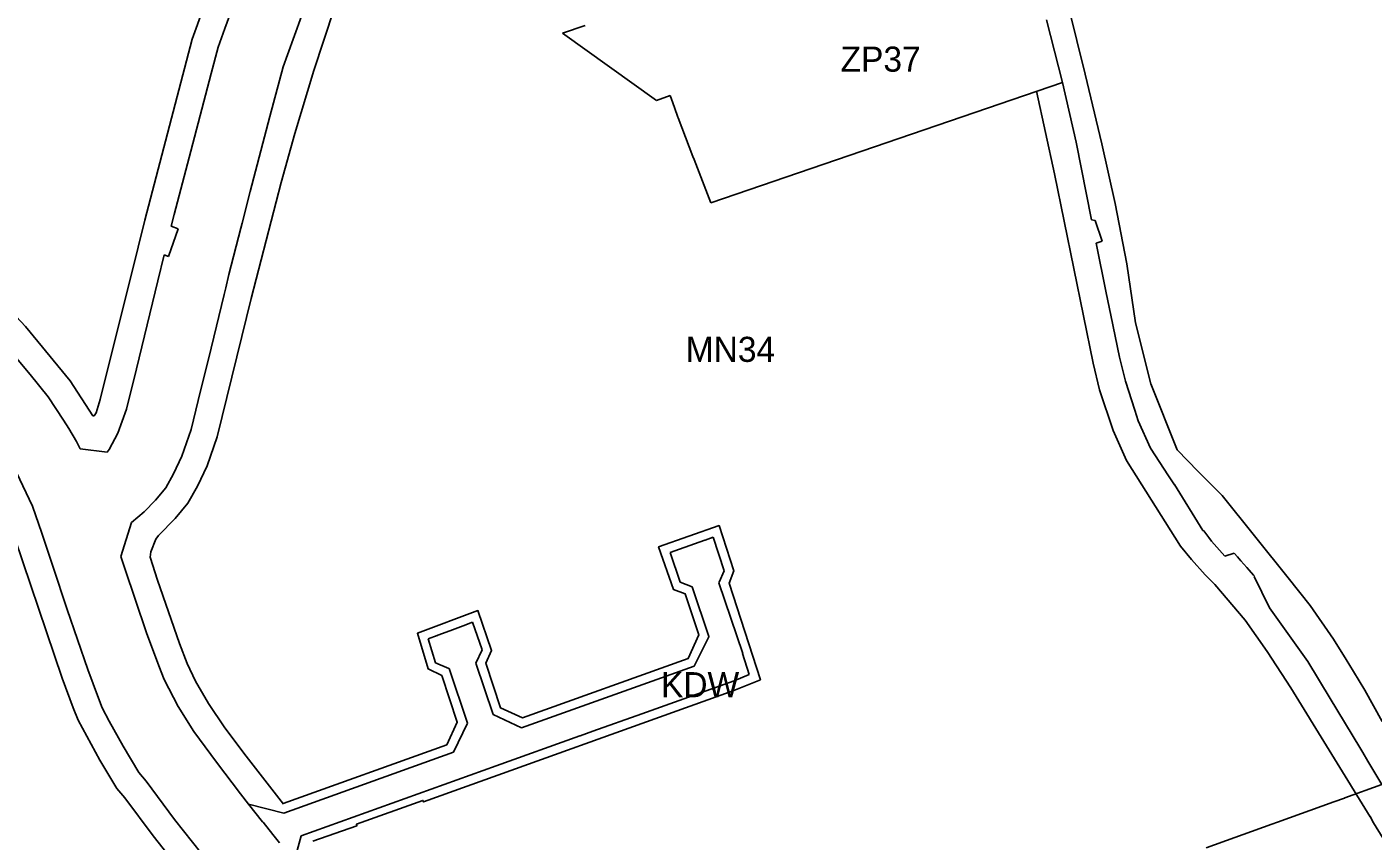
# Model space of a CAD drawing. Extents: x 7428080 to 7432143, y 5545880 to 5549217.
# Drawn here: x 7430887.1 to 7431185, y 5546851.1 to 5547031.3 of the extents above; entities that cross this region are included whole.
import ezdxf

# ---------------------------------------------------------------- set-up
doc = ezdxf.new("R2010")
doc.units = 0
for name, color, linetype in [('CZ_L_granica obszaru objętego planem', 7, 'Continuous'), ('CZ_L_linie rozgraniczające tereny o różnym przeznaczeniu oraz różnych warunkach ich zabudowy i zagospodarowania', 7, 'Continuous'), ('CZ_L_maksymalne nieprzekraczalne linie zabudowy', 7, 'Continuous'), ('CZ_L_opisy_linie rozgraniczające tereny o różnym przeznaczeniu oraz różnych warunkach ich zabudowy i zagospodarowania', 7, 'Continuous')]:
    doc.layers.add(name, color=color, linetype=linetype)

msp = doc.modelspace()

# ---------------------------------------------------------------- linework, layer by layer
at = {"layer": 'CZ_L_granica obszaru objętego planem'}
for p, q in [((7431117.61, 5547035.75), (7431121.32, 5547020.82)), ((7431121.32, 5547020.82), (7431125.01, 5547005.39)), ((7431125.01, 5547005.39), (7431127.96, 5546992.25)), ((7431127.96, 5546992.25), (7431130.5, 5546978.83)), ((7431130.5, 5546978.83), (7431132.44, 5546965.83)), ((7431132.44, 5546965.83), (7431135.86, 5546952.34)), ((7431135.86, 5546952.34), (7431141.66, 5546937.67)), ((7431141.66, 5546937.67), (7431146.32, 5546932.9)), ((7431146.32, 5546932.9), (7431151.59, 5546927.62)), ((7431151.59, 5546927.62), (7431166.27, 5546909.37)), ((7431166.27, 5546909.37), (7431171.08, 5546903.28)), ((7431171.08, 5546903.28), (7431176.28, 5546895.82)), ((7431176.28, 5546895.82), (7431179.09, 5546891.28)), ((7431179.09, 5546891.28), (7431180.72, 5546888.65)), ((7431180.72, 5546888.65), (7431183.18, 5546884.54)), ((7431183.18, 5546884.54), (7431187.05, 5546877.6))]:
    msp.add_line(p, q, dxfattribs=at)
at = {"layer": 'CZ_L_linie rozgraniczające tereny o różnym przeznaczeniu oraz różnych warunkach ich zabudowy i zagospodarowania'}
for p, q in [((7430936.02, 5547045.16), (7430930.9, 5547030.96)), ((7430949.44, 5547038.17), (7430944.73, 5547025.11)), ((7431112.76, 5547032.83), (7431116.28, 5547019.02)), ((7430930.9, 5547030.96), (7430929.41, 5547026.79)), ((7431005.65, 5547029.91), (7431010.64, 5547031.63)), ((7431026.39, 5547015), (7431005.65, 5547029.91)), ((7430929.41, 5547026.79), (7430927.87, 5547020.98)), ((7430944.73, 5547025.11), (7430943.77, 5547022.44)), ((7430927.87, 5547020.98), (7430923.36, 5547003.83)), ((7430943.77, 5547022.44), (7430940.87, 5547011.44)), ((7431116.26, 5547019.01), (7431038.48, 5546992.34)), ((7431116.28, 5547019.02), (7431116.26, 5547019.01)), ((7431119.3, 5547005.78), (7431116.26, 5547019.01)), ((7431029.46, 5547016.12), (7431026.39, 5547015)), ((7431030.02, 5547014.46), (7431029.46, 5547016.12)), ((7431030.99, 5547011.78), (7431030.02, 5547014.46)), ((7431031.15, 5547011.36), (7431030.99, 5547011.78)), ((7430940.87, 5547011.44), (7430936.51, 5546994.87)), ((7431031.21, 5547011.17), (7431031.15, 5547011.36)), ((7431034.49, 5547002.62), (7431031.21, 5547011.17)), ((7431122.71, 5546988.6), (7431119.3, 5547005.78)), ((7430923.36, 5547003.83), (7430919.67, 5546989.77)), ((7431034.75, 5547001.96), (7431034.49, 5547002.62)), ((7431038.48, 5546992.34), (7431034.75, 5547001.96)), ((7430936.51, 5546994.87), (7430934.68, 5546987.9)), ((7430919.67, 5546989.77), (7430919.02, 5546987.17)), ((7430934.68, 5546987.9), (7430934.39, 5546986.78)), ((7431123.53, 5546988.45), (7431122.71, 5546988.6)), ((7431125.1, 5546983.87), (7431123.53, 5546988.45)), ((7430920.58, 5546986.61), (7430918.44, 5546980.5)), ((7430919.02, 5546987.17), (7430920.58, 5546986.61)), ((7430934.4, 5546986.77), (7430931.8, 5546976.53)), ((7430934.39, 5546986.78), (7430934.4, 5546986.77)), ((7431123.75, 5546983.44), (7431125.1, 5546983.87)), ((7431125.96, 5546972.48), (7431123.75, 5546983.44)), ((7430917.45, 5546980.85), (7430916.02, 5546975.09)), ((7430918.44, 5546980.5), (7430917.45, 5546980.85)), ((7430931.8, 5546976.53), (7430931.07, 5546973.52)), ((7430916.02, 5546975.09), (7430911.29, 5546955.65)), ((7430931.07, 5546973.52), (7430930.72, 5546972.09)), ((7430930.72, 5546972.09), (7430927.83, 5546960.2)), ((7431126.97, 5546967.49), (7431125.96, 5546972.48)), ((7431128.88, 5546958.21), (7431126.97, 5546967.49)), ((7430887.76, 5546954.35), (7430882.17, 5546961.12)), ((7430927.83, 5546960.2), (7430925.01, 5546948.6)), ((7431130.2, 5546952.91), (7431128.88, 5546958.21)), ((7430911.29, 5546955.65), (7430909.11, 5546946.68)), ((7430891.79, 5546949.43), (7430887.76, 5546954.35)), ((7431132.27, 5546946.49), (7431130.2, 5546952.91)), ((7430895.18, 5546944.25), (7430891.79, 5546949.43)), ((7430909.11, 5546946.68), (7430907.21, 5546941.43)), ((7430925.01, 5546948.6), (7430923.44, 5546942.19)), ((7431133.07, 5546944.12), (7431132.27, 5546946.49)), ((7430896.38, 5546942.4), (7430895.18, 5546944.25)), ((7431135.77, 5546938.09), (7431133.07, 5546944.12)), ((7430898.08, 5546939.56), (7430896.38, 5546942.4)), ((7430907.21, 5546941.43), (7430905.29, 5546937.76)), ((7430923.44, 5546942.19), (7430921.35, 5546936.31)), ((7430898.86, 5546937.95), (7430898.08, 5546939.56)), ((7430904.81, 5546937.18), (7430898.86, 5546937.95)), ((7430905.29, 5546937.76), (7430904.81, 5546937.18)), ((7431139.75, 5546931.97), (7431135.77, 5546938.09)), ((7430921.35, 5546936.31), (7430919.49, 5546932.37)), ((7430884.75, 5546932.69), (7430888.34, 5546925.21)), ((7430919.49, 5546932.37), (7430917.8, 5546929.33)), ((7431141.07, 5546929.94), (7431139.75, 5546931.97)), ((7430917.8, 5546929.33), (7430915.5, 5546926.59)), ((7431141.1, 5546930.02), (7431141.07, 5546929.94)), ((7431147.35, 5546919.85), (7431141.1, 5546930.02)), ((7430888.34, 5546925.21), (7430890.39, 5546919.28)), ((7430915.5, 5546926.59), (7430913.05, 5546923.97)), ((7430913.05, 5546923.97), (7430910.25, 5546921.64)), ((7430890.39, 5546919.28), (7430892.78, 5546911.95)), ((7430910.25, 5546921.62), (7430907.85, 5546914.13)), ((7430910.25, 5546921.64), (7430910.25, 5546921.62)), ((7431147.59, 5546919.77), (7431147.35, 5546919.85)), ((7431148.66, 5546918.34), (7431147.59, 5546919.77)), ((7431037.09, 5546917.69), (7431031.54, 5546915.74)), ((7431037.2, 5546917.73), (7431037.09, 5546917.69)), ((7431038.98, 5546918.36), (7431037.2, 5546917.73)), ((7431041.43, 5546910.93), (7431038.98, 5546918.36)), ((7431149.28, 5546917.49), (7431148.66, 5546918.34)), ((7431152.18, 5546914.2), (7431149.28, 5546917.49)), ((7430907.85, 5546914.13), (7430908.81, 5546911.24)), ((7431031.54, 5546915.74), (7431029.42, 5546914.99)), ((7431029.42, 5546914.99), (7431031.64, 5546908.41)), ((7431154.31, 5546914.81), (7431152.18, 5546914.2)), ((7431155, 5546914.02), (7431154.31, 5546914.81)), ((7431155.77, 5546913.14), (7431155, 5546914.02)), ((7430892.78, 5546911.95), (7430895.98, 5546902.37)), ((7430908.81, 5546911.24), (7430911.04, 5546904.66)), ((7431040.29, 5546908.4), (7431041.43, 5546910.93)), ((7431157.07, 5546911.67), (7431155.77, 5546913.14)), ((7431157.63, 5546911.04), (7431157.07, 5546911.67)), ((7431158.55, 5546909.99), (7431157.63, 5546911.04)), ((7431031.64, 5546908.41), (7431034.3, 5546907.42)), ((7431034.3, 5546907.42), (7431034.33, 5546907.41)), ((7431034.33, 5546907.41), (7431038.02, 5546896.42)), ((7431040.25, 5546908.3), (7431040.29, 5546908.4)), ((7431045.5, 5546892.67), (7431040.25, 5546908.3)), ((7431158.75, 5546909.76), (7431158.55, 5546909.99)), ((7431158.74, 5546909.71), (7431158.75, 5546909.76)), ((7431162.09, 5546902.77), (7431158.74, 5546909.71)), ((7430911.04, 5546904.66), (7430913.57, 5546897.22)), ((7430895.98, 5546902.37), (7430900.53, 5546889.1)), ((7431170.57, 5546890.86), (7431162.09, 5546902.77)), ((7430983.63, 5546898.78), (7430980.68, 5546897.67)), ((7430985.73, 5546899.56), (7430983.63, 5546898.77)), ((7430983.63, 5546898.77), (7430983.63, 5546898.78)), ((7430987.81, 5546893.42), (7430985.73, 5546899.56)), ((7430913.57, 5546897.22), (7430916.27, 5546889.89)), ((7430977.88, 5546896.62), (7430975.86, 5546895.87)), ((7430975.86, 5546895.87), (7430977.54, 5546890.6)), ((7430978.03, 5546896.59), (7430977.88, 5546896.62)), ((7430980.68, 5546897.67), (7430978.01, 5546896.66)), ((7430978.01, 5546896.66), (7430978.03, 5546896.59)), ((7431037.97, 5546896.32), (7431034.78, 5546889.84)), ((7431038.02, 5546896.42), (7431037.97, 5546896.32)), ((7430986.42, 5546890.53), (7430987.81, 5546893.42)), ((7431046.95, 5546887.98), (7431045.49, 5546892.67)), ((7431045.49, 5546892.67), (7431045.5, 5546892.67)), ((7430916.27, 5546889.89), (7430917.42, 5546886.87)), ((7430977.54, 5546890.6), (7430980.49, 5546889.3)), ((7430990.27, 5546879.15), (7430986.42, 5546890.53)), ((7431034.78, 5546889.84), (7431021.35, 5546885.03)), ((7431175.52, 5546882.67), (7431170.57, 5546890.86)), ((7430900.53, 5546889.1), (7430902.94, 5546882.76)), ((7430917.42, 5546886.87), (7430920.57, 5546880.87)), ((7430980.49, 5546889.3), (7430980.51, 5546889.29)), ((7430980.51, 5546889.29), (7430984.59, 5546877.25)), ((7431023.17, 5546879.31), (7431043.6, 5546886.62)), ((7431043.6, 5546886.62), (7431046.95, 5546887.98)), ((7431021.35, 5546885.03), (7430996.51, 5546876.19)), ((7430902.94, 5546882.76), (7430903.76, 5546880.64)), ((7430903.76, 5546880.64), (7430905.3, 5546877.69)), ((7430920.57, 5546880.87), (7430924.01, 5546875.39)), ((7431182.06, 5546871.83), (7431175.52, 5546882.67)), ((7430905.3, 5546877.69), (7430908.35, 5546872.11)), ((7430996.51, 5546876.19), (7430990.27, 5546879.15)), ((7431012.31, 5546875.42), (7431023.17, 5546879.31)), ((7430924.01, 5546875.39), (7430929.02, 5546868.61)), ((7430984.57, 5546877.21), (7430981.51, 5546870.83)), ((7430984.59, 5546877.25), (7430984.57, 5546877.21)), ((7431009.49, 5546874.41), (7431012.31, 5546875.42)), ((7430908.35, 5546872.11), (7430911.85, 5546866.31)), ((7430990.9, 5546867.74), (7431009.48, 5546874.4)), ((7431009.48, 5546874.4), (7431009.49, 5546874.41)), ((7431009.49, 5546874.41), (7431009.49, 5546874.41)), ((7431182.74, 5546870.7), (7431182.06, 5546871.83)), ((7430929.02, 5546868.61), (7430934.34, 5546861.59)), ((7430981.51, 5546870.83), (7430943.93, 5546857.28)), ((7431183.87, 5546868.83), (7431182.74, 5546870.7)), ((7431187, 5546863.62), (7431183.87, 5546868.83)), ((7430911.85, 5546866.31), (7430913.46, 5546864.37)), ((7430947.77, 5546852.28), (7430990.9, 5546867.74)), ((7430913.46, 5546864.37), (7430919.75, 5546855.93)), ((7431178.79, 5546860.67), (7431187, 5546863.62)), ((7430934.34, 5546861.59), (7430936.15, 5546859.31)), ((7431163.85, 5546855.3), (7431176.35, 5546859.79)), ((7431176.35, 5546859.79), (7431178.68, 5546860.63)), ((7431178.68, 5546860.63), (7431178.79, 5546860.67)), ((7430943.93, 5546857.28), (7430936.15, 5546859.31)), ((7430936.15, 5546859.31), (7430939.25, 5546855.4)), ((7430919.75, 5546855.93), (7430925.7, 5546848.35)), ((7430939.25, 5546855.4), (7430939.32, 5546855.31)), ((7430939.32, 5546855.31), (7430939.34, 5546855.29)), ((7430939.34, 5546855.29), (7430941.47, 5546852.61)), ((7431148.11, 5546849.64), (7431162.61, 5546854.85)), ((7431162.61, 5546854.85), (7431163.85, 5546855.3)), ((7430941.47, 5546852.61), (7430942.98, 5546850.71)), ((7430946.25, 5546846.58), (7430947.77, 5546852.28))]:
    msp.add_line(p, q, dxfattribs=at)
msp.add_lwpolyline([(7431117.6, 5547035.79), (7431117.61, 5547035.75), (7431121.32, 5547020.82), (7431125.01, 5547005.39), (7431127.96, 5546992.25), (7431130.5, 5546978.83), (7431132.44, 5546965.83), (7431135.86, 5546952.34), (7431141.66, 5546937.67), (7431146.32, 5546932.9), (7431151.59, 5546927.62), (7431166.27, 5546909.37), (7431171.08, 5546903.28), (7431176.28, 5546895.82), (7431179.09, 5546891.28), (7431180.72, 5546888.65), (7431183.18, 5546884.54), (7431187.05, 5546877.6)], dxfattribs=at)
at = {"layer": 'CZ_L_maksymalne nieprzekraczalne linie zabudowy'}
for points in [[(7430654.54, 5547240.29), (7430665.61, 5547225.73), (7430675.78, 5547211.67), (7430680.29, 5547205.95), (7430715.45, 5547163.65), (7430765.79, 5547100.82), (7430780.35, 5547083.28), (7430800.05, 5547059.92), (7430816.12, 5547041.16), (7430824.8, 5547031.35), (7430886.76, 5546964.98), (7430896.64, 5546952.97), (7430901.69, 5546945.24), (7430901.95, 5546945.2), (7430902.39, 5546945.93), (7430903.3, 5546948.81), (7430911.71, 5546982.58), (7430913.18, 5546988.55), (7430923.67, 5547028.55), (7430938.24, 5547068.96)], [(7431001.77, 5546688.14), (7430985.61, 5546730.31), (7430971.26, 5546768.92), (7430965.85, 5546780.6), (7430952.8, 5546802.25), (7430945.6, 5546813.48), (7430915, 5546852.27), (7430908.72, 5546860.69), (7430907, 5546862.78), (7430903.21, 5546869.02), (7430898.44, 5546877.88), (7430897.33, 5546880.63), (7430894.86, 5546887.15), (7430882.68, 5546923.15), (7430879.42, 5546929.87), (7430874.82, 5546937.03), (7430866.55, 5546947.03), (7430812.62, 5547004.67), (7430797.81, 5547020.91), (7430765.98, 5547058.41), (7430743.74, 5547085.12), (7430692.31, 5547149.26)], [(7431072.4, 5547053.11), (7430990.73, 5547105.56), (7430988.19, 5547104.82), (7430986.23, 5547103.84), (7430984.69, 5547102.6), (7430982.99, 5547100.5), (7430975.84, 5547088.45), (7430971.39, 5547079.97), (7430967.74, 5547071), (7430957.36, 5547042.33), (7430950.55, 5547021.67), (7430946.38, 5547007.73), (7430943.31, 5546996.83), (7430936.67, 5546971.18)], [(7431142.42, 5546916.42), (7431130.43, 5546935.36), (7431127.48, 5546941.96), (7431124.51, 5546951.01), (7431123.04, 5546956.85), (7431114.54, 5546998.81), (7431110.55, 5547017.08)], [(7430936.75, 5546971.47), (7430929.21, 5546940.55), (7430926.96, 5546934.18), (7430924.83, 5546929.63), (7430922.7, 5546925.87), (7430919.91, 5546922.53), (7430916.23, 5546918.77), (7430915.6, 5546917.93), (7430914.53, 5546915.1), (7430914.38, 5546913.96), (7430915.95, 5546908.89), (7430920.85, 5546894.84), (7430922.51, 5546890.43), (7430924.41, 5546886.5), (7430927.23, 5546881.58), (7430930.89, 5546876.21), (7430935.58, 5546869.9), (7430943.84, 5546859.3)], [(7430943.81, 5546859.42), (7430979.99, 5546872.45), (7430982.31, 5546877.45), (7430978.9, 5546887.74), (7430975.91, 5546889.22), (7430973.5, 5546897.12), (7430986.89, 5546902.13), (7430989.93, 5546893.32), (7430988.63, 5546890.52), (7430991.92, 5546880.61), (7430996.77, 5546878.39), (7431033.46, 5546891.56), (7431035.79, 5546896.8), (7431032.74, 5546905.86), (7431030.15, 5546906.81), (7431026.89, 5546916.22), (7431040.26, 5546920.93), (7431043.54, 5546910.9), (7431042.5, 5546908.21), (7431049.41, 5546886.83), (7431043.57, 5546884.44), (7430974.85, 5546859.79), (7430974.73, 5546860.14), (7430960, 5546854.86), (7430960.12, 5546854.51), (7430950.34, 5546851.14)], [(7431184.36, 5546856.51), (7431166.85, 5546885.05), (7431161.58, 5546893.07), (7431156.75, 5546900.01), (7431150, 5546907.93), (7431147.83, 5546910.07), (7431144.84, 5546913.46), (7431142.44, 5546916.41)], [(7431141.98, 5546734.3), (7431201.48, 5546756.15), (7431213.71, 5546759.85), (7431227.5, 5546763.18), (7431238.99, 5546764.95), (7431252.37, 5546765.87), (7431257.66, 5546765.8), (7431269.33, 5546763.72), (7431268.74, 5546769.43), (7431267.3, 5546771.6), (7431231.51, 5546796.51), (7431229.84, 5546798.06), (7431212.56, 5546817.77), (7431193.31, 5546842.22), (7431189.98, 5546847.26), (7431185.11, 5546855.13), (7431184.36, 5546856.6)]]:
    msp.add_lwpolyline(points, dxfattribs=at)

# ---------------------------------------------------------------- texts
at = {"layer": 'CZ_L_opisy_linie rozgraniczające tereny o różnym przeznaczeniu oraz różnych warunkach ich zabudowy i zagospodarowania'}
for s, p in [('ZP37', (7431067.16, 5547021.39)), ('MN34', (7431032.89, 5546957.17)), ('KDW', (7431027.41, 5546882.96))]:
    msp.add_text(s, height=5.549, dxfattribs=at).set_placement(p)

doc.saveas('drawing.dxf')
